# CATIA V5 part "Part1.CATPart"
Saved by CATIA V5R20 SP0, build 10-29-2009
Part number: Part1
Bounding box of the stored display mesh (mm): x -5 to 10, y 0 to 100, z -5 to 5
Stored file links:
  E:\Ehsan\Catia\Tamrin\Digital Mockup\4\Part1.CATPart
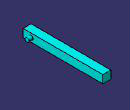
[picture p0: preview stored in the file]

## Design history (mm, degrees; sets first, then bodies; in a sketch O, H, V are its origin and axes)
Body1 (main body)
  Sketch1 on zx-plane, origin (0, 0, 0), H (-1, 0, 0), V (0, 0, 1)
    line L1 (5, 5) -> (5, -5)
    line L2 (5, -5) -> (-5, -5)
    line L3 (-5, -5) -> (-5, 5)
    line L4 (-5, 5) -> (5, 5)
    distance L2 L4 = 10
    distance L1 L3 = 10
    vertical: L1 V, L3 V
    horizontal: L2 H, L4 H
    equidistance: L1 L3 O, L2 L4 O
  Pad1: profile Sketch1, direction (0, 1, 0), length 100
  Sketch2 on face of Pad1 from Sketch1.L3, origin (5, 0, 0), H (0, 1, 0), V (0, 0, 1)
    circle A1 centre (10, 0) radius 2.5
    point P1 (10, 0)
    distance P1 V = 10
    distance P1 H = 0
    radius A1 = 2.5
  Pad2: profile Sketch2, direction (1, 0, 0), length 5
